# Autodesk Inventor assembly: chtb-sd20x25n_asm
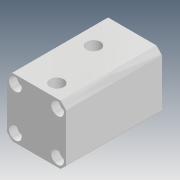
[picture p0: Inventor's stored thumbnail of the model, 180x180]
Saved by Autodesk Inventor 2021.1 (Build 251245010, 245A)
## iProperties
Company: Microsoft
Created: 2018-04
Part Number: chtb-sd20x25n_asm
Description: STEP AP214
Document SubType Name: Assembly
Designer: user
Title: chtb-sd20x25n_asm.STEP
Author: Windows
Revision Number: ÈÎºÎ
Sending System: SolidWorks 2015
Preprocessor: SwSTEP 2.0
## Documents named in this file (4)
- D:\Vault_2016\Projekty\Clamptek\Hydraulic\CHTB\CHTB-20\Inventor\CHTB-SD20x25N\chtb-sd20x25n_asm.iam
- D:\Vault_2016\Projekty\Clamptek\Hydraulic\CHTB\CHTB-20\Inventor\CHTB-SD20x25N\CHTB-SD20X25NBT.ipt
- D:\Vault_2016\Projekty\Clamptek\Hydraulic\CHTB\CHTB-20\Inventor\CHTB-SD20x25N\CHTB-SD20X25NHSG.ipt
- D:\Vault_2016\Projekty\Clamptek\Hydraulic\CHTB\CHTB-20\Inventor\CHTB-SD20x25N\QG.ipt
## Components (3 placed, 3 different names)
1. CHTB-SD20X25NBT_1
2. CHTB-SD20X25NHSG_2
3. QG_3
